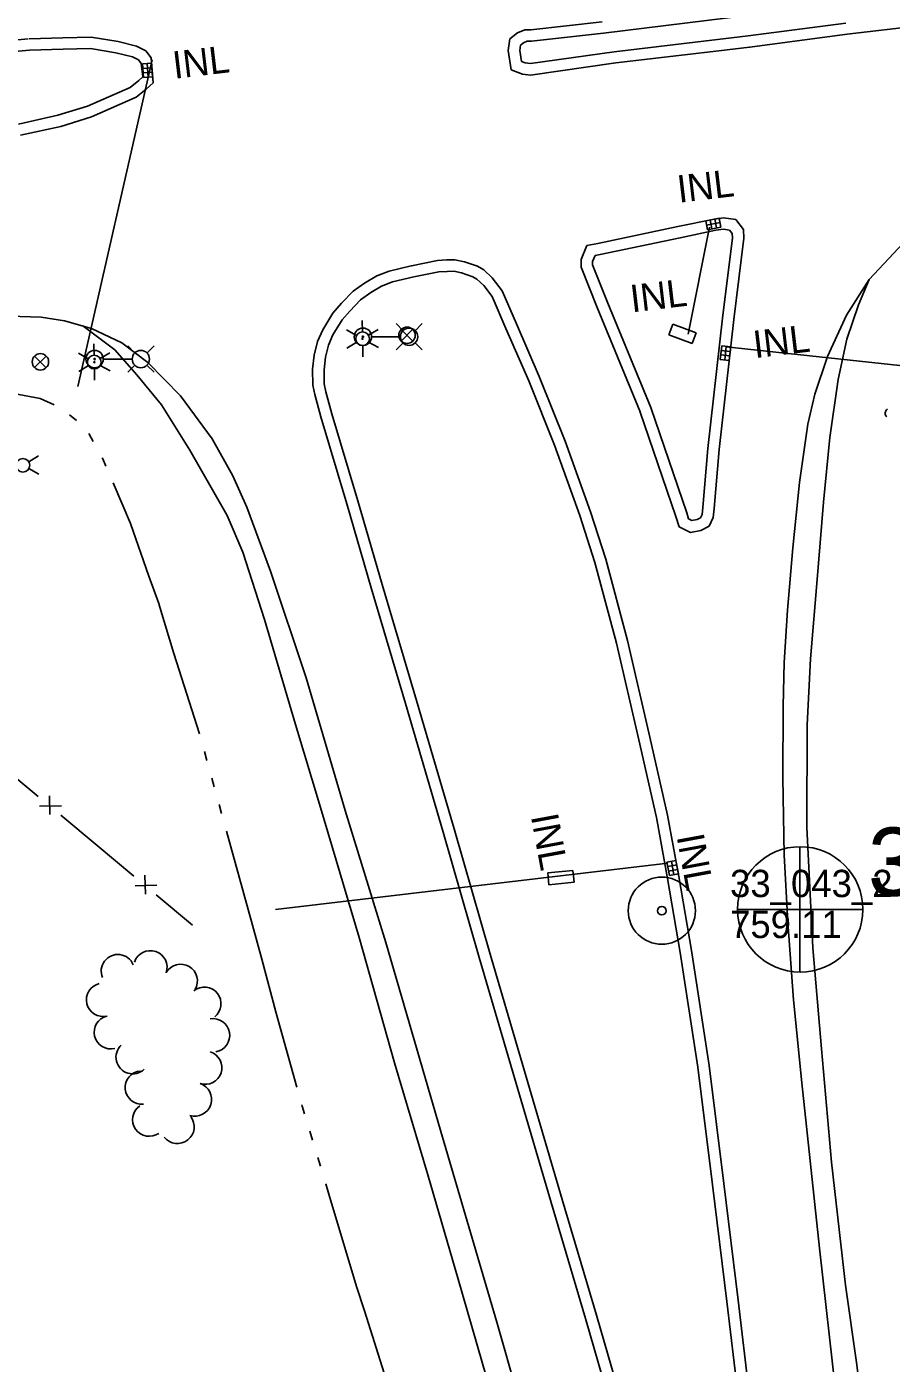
# Model space of a CAD drawing. Extents: x 589250 to 1188077, y 162953 to 363065.
# Drawn here: x 594538 to 594728, y 174624.2 to 174918 of the extents above; entities that cross this region are included whole.
import ezdxf

# ---------------------------------------------------------------- set-up
doc = ezdxf.new("R2010")
doc.units = 0
for name, color, linetype in [('E_DRN', 7, 'Continuous'), ('E_DRN_SS_UG', 7, 'Continuous'), ('E_DRN_Text', 7, 'Continuous'), ('E_FEN_P', 7, 'Continuous'), ('E_LAND_TreeLine_P', 7, 'Continuous'), ('E_LTG', 7, 'Continuous'), ('E_MAP_PassPoints', 7, 'Continuous'), ('E_MAP_PhotoCenter', 7, 'Continuous'), ('E_RDWY', 7, 'Continuous'), ('E_RDWY_C_and_G', 7, 'Continuous'), ('E_RDWY_Gravel', 7, 'Continuous'), ('E_SIG', 7, 'Continuous'), ('E_WTR_FlowLine', 7, 'Continuous')]:
    doc.layers.add(name, color=color, linetype=linetype)

# ---------------------------------------------------------------- blocks, each defined once
blk = doc.blocks.new('LPM_1')
at = {"layer": 'E_LTG'}
for p, q in [((32.9, 0), (7.7, 0)), ((35.3, 5.3), (29.1, 11.6)), ((46, 5.3), (52.2, 11.6)), ((35.3, -5.3), (29.1, -11.6)), ((46, -5.3), (52.2, -11.6))]:
    blk.add_line(p, q, dxfattribs=at)
for centre, radius in [((0, 0), 7.62), ((0, 0), 0.583), ((40.6, 0), 7.62)]:
    blk.add_circle(centre, radius, dxfattribs=at)
blk = doc.blocks.new('PBX_2')
at = {"layer": 'E_SIG'}
for p, q in [((4.9, 5.1), (-5.1, -5.1)), ((-5.1, 5), (5, -5.2))]:
    blk.add_line(p, q, dxfattribs=at)
blk.add_circle((0, 0), 7.21, dxfattribs=at)

msp = doc.modelspace()

# ---------------------------------------------------------------- linework, layer by layer
at = {"layer": 'E_DRN'}
for p, q in [((594565.41, 174909.94), (594563.41, 174909.8)), ((594563.41, 174909.8), (594563.62, 174906.81)), ((594563.48, 174908.8), (594565.48, 174908.95)), ((594563.55, 174907.81), (594565.55, 174907.95)), ((594564.62, 174906.88), (594564.41, 174909.87)), ((594565.62, 174906.95), (594565.41, 174909.94)), ((594563.62, 174906.81), (594565.62, 174906.95)), ((594690.15, 174875.88), (594687.2, 174875.29)), ((594687.2, 174875.29), (594687.59, 174873.33)), ((594688.57, 174873.53), (594688.18, 174875.49)), ((594689.56, 174873.72), (594689.17, 174875.68)), ((594690.54, 174873.92), (594690.15, 174875.88)), ((594690.34, 174874.9), (594687.4, 174874.31)), ((594687.59, 174873.33), (594690.54, 174873.92)), ((594679.1, 174850.24), (594679.99, 174852.58)), ((594679.99, 174852.58), (594685.11, 174850.64)), ((594684.22, 174848.3), (594679.1, 174850.24)), ((594685.11, 174850.64), (594684.22, 174848.3)), ((594690.73, 174847.81), (594690.39, 174844.82)), ((594690.5, 174845.82), (594692.49, 174845.59)), ((594690.61, 174846.81), (594692.6, 174846.59)), ((594692.71, 174847.58), (594690.73, 174847.81)), ((594691.38, 174844.71), (594691.72, 174847.69)), ((594692.37, 174844.6), (594692.71, 174847.58)), ((594690.39, 174844.82), (594692.37, 174844.6)), ((594680.64, 174734.72), (594678.67, 174734.36)), ((594678.67, 174734.36), (594679.22, 174731.41)), ((594680.2, 174731.59), (594679.66, 174734.54)), ((594681.19, 174731.77), (594680.64, 174734.72)), ((594658.01, 174732.52), (594652.47, 174731.97)), ((594652.47, 174731.97), (594652.73, 174729.38)), ((594658.26, 174729.93), (594658.01, 174732.52)), ((594678.86, 174733.37), (594680.82, 174733.74)), ((594679.04, 174732.39), (594681, 174732.75)), ((594679.22, 174731.41), (594681.19, 174731.77)), ((594652.73, 174729.38), (594658.26, 174729.93))]:
    msp.add_line(p, q, dxfattribs=at)
msp.add_arc((594727.7, 174833), 1.04, 122.955, 229.2152, dxfattribs=at)
at = {"layer": 'E_DRN_SS_UG'}
for p, q in [((594565.55, 174910.71), (594549.19, 174838.9)), ((594683.36, 174850.39), (594688.06, 174873.91)), ((594691.68, 174847.61), (594766.96, 174839.54)), ((594678.84, 174734.13), (594592.64, 174723.97))]:
    msp.add_line(p, q, dxfattribs=at)
at = {"layer": 'E_FEN_P'}
for p, q in [((594532.46, 174755.44), (594540.47, 174748.77)), ((594542.92, 174748.95), (594543.04, 174744.82)), ((594540.77, 174746.62), (594545.59, 174746.73)), ((594545.44, 174744.64), (594553.45, 174737.97)), ((594553.45, 174737.97), (594561.47, 174731.29)), ((594563.92, 174731.47), (594564.04, 174727.34)), ((594561.77, 174729.14), (594566.58, 174729.25)), ((594566.43, 174727.16), (594574.42, 174720.46))]:
    msp.add_line(p, q, dxfattribs=at)
at = {"layer": 'E_LAND_TreeLine_P'}
for centre, start, end in [((594557.99, 174710.39), 22.8086, 202.8086), ((594565.13, 174711.22), 341.3534, 161.3534), ((594571.79, 174708.23), 329.5776, 149.5776), ((594554.74, 174704.09), 103.536, 283.536), ((594576.99, 174703.22), 308.4125, 128.4125), ((594556.45, 174696.95), 103.536, 283.536), ((594578.91, 174696.29), 279.5379, 99.5379), ((594561.24, 174691.49), 133.4046, 313.4046), ((594577.17, 174689.18), 252.1211, 72.1211), ((594563.27, 174684.79), 95.4059, 275.4059), ((594574.92, 174682.19), 252.1211, 72.1211), ((594564.9, 174677.76), 124.6972, 304.6972), ((594571.09, 174676.18), 217.8771, 37.8771)]:
    msp.add_arc(centre, 3.67, start, end, dxfattribs=at)
at = {"layer": 'E_LTG'}
for p, q in [((594611.74, 174850.87), (594611.7, 174853.37)), ((594610.46, 174850.09), (594608.27, 174851.31)), ((594615.2, 174851.43), (594613.06, 174850.14)), ((594551.49, 174844.97), (594549.3, 174846.18)), ((594552.77, 174845.74), (594552.73, 174848.24)), ((594556.23, 174846.3), (594554.08, 174845.02)), ((594610.49, 174848.59), (594608.34, 174847.31)), ((594611.84, 174845.37), (594611.8, 174847.87)), ((594615.27, 174847.43), (594613.08, 174848.64)), ((594551.51, 174843.47), (594549.37, 174842.18)), ((594556.3, 174842.31), (594554.11, 174843.52)), ((594552.87, 174840.24), (594552.83, 174842.74)), ((594540.54, 174823.62), (594538.4, 174822.33)), ((594540.61, 174819.62), (594538.43, 174820.83))]:
    msp.add_line(p, q, dxfattribs=at)
for centre, radius in [((594611.77, 174849.37), 1.5), ((594611.77, 174849.37), 0.125), ((594552.8, 174844.24), 1.5), ((594552.8, 174844.24), 0.125), ((594537.11, 174821.56), 1.5)]:
    msp.add_circle(centre, radius, dxfattribs=at)
at = {"layer": 'E_MAP_PassPoints'}
for radius in [7.38, 7.38, 0.945, 0.945]:
    msp.add_circle((594677.55, 174723.68), radius, dxfattribs=at)
at = {"layer": 'E_MAP_PhotoCenter'}
for p, q in [((594707.92, 174737.76), (594707.86, 174710.35)), ((594694.23, 174723.95), (594721.69, 174723.94))]:
    msp.add_line(p, q, dxfattribs=at)
msp.add_circle((594707.97, 174723.96), 13.78, dxfattribs=at)
at = {"layer": 'E_RDWY'}
for p, q in [((594723.09, 174862.4), (594730.6, 174870.37)), ((594718.14, 174854.58), (594723.09, 174862.4)), ((594531.74, 174854.42), (594541.14, 174854.09)), ((594541.14, 174854.09), (594546.26, 174853.35)), ((594546.26, 174853.35), (594552.22, 174851.64)), ((594713.93, 174845.5), (594718.14, 174854.58)), ((594552.22, 174851.64), (594558.87, 174848.47)), ((594558.87, 174848.47), (594564.55, 174844.12)), ((594564.55, 174844.12), (594571.76, 174836.83)), ((594711.17, 174837.22), (594713.93, 174845.5)), ((594709.62, 174830.59), (594711.17, 174837.22)), ((594571.76, 174836.83), (594578.68, 174827.39)), ((594707.84, 174817.81), (594709.62, 174830.59)), ((594578.68, 174827.39), (594583.28, 174819.23)), ((594583.28, 174819.23), (594586.36, 174812.36)), ((594706.33, 174803.39), (594707.84, 174817.81)), ((594586.36, 174812.36), (594591.56, 174798.28)), ((594705.19, 174789.7), (594706.33, 174803.39)), ((594591.56, 174798.28), (594599.38, 174774.86)), ((594704.46, 174778.22), (594705.19, 174789.7)), ((594704.25, 174768.64), (594704.46, 174778.22)), ((594599.38, 174774.86), (594607.97, 174745.67)), ((594704.15, 174752.86), (594704.25, 174768.64)), ((594704.45, 174735.95), (594704.15, 174752.86)), ((594607.97, 174745.67), (594616.89, 174716.66)), ((594705.27, 174721.13), (594704.45, 174735.95)), ((594706.51, 174704.05), (594705.27, 174721.13)), ((594616.89, 174716.66), (594628.99, 174675.18)), ((594708.33, 174685.86), (594706.51, 174704.05)), ((594712.17, 174649.48), (594708.33, 174685.86)), ((594628.99, 174675.18), (594641.26, 174633.21)), ((594716.16, 174614.61), (594712.17, 174649.48)), ((594641.26, 174633.21), (594655.48, 174583.86))]:
    msp.add_line(p, q, dxfattribs=at)
at = {"layer": 'E_RDWY_C_and_G'}
for p, q in [((594696.29, 174920.4), (594664.72, 174916.55)), ((594752.76, 174920.45), (594718.31, 174916.29)), ((594645.85, 174916.6), (594644.12, 174915.26)), ((594647.42, 174917.26), (594645.85, 174916.6)), ((594648.77, 174917.29), (594647.42, 174917.26)), ((594664.43, 174919.03), (594648.77, 174917.29)), ((594664.72, 174916.55), (594648.93, 174914.79)), ((594717.99, 174918.77), (594696.54, 174915.95)), ((594526.33, 174914.19), (594538.3, 174915.3)), ((594538.45, 174915.31), (594545.88, 174915.54)), ((594545.88, 174915.54), (594552.15, 174915.65)), ((594552.15, 174915.65), (594558.03, 174914.7)), ((594558.03, 174914.7), (594562.09, 174913.68)), ((594562.09, 174913.68), (594564.13, 174912.63)), ((594644.12, 174915.26), (594643.81, 174912.73)), ((594646.48, 174913.92), (594646.33, 174912.76)), ((594647.13, 174914.43), (594646.48, 174913.92)), ((594647.94, 174914.77), (594647.13, 174914.43)), ((594648.93, 174914.79), (594647.94, 174914.77)), ((594667.1, 174912.47), (594689.79, 174915.18)), ((594689.79, 174915.18), (594696.54, 174915.95)), ((594690.09, 174912.69), (594696.82, 174913.47)), ((594718.31, 174916.29), (594696.86, 174913.48)), ((594526.59, 174911.71), (594538.53, 174912.81)), ((594538.53, 174912.81), (594545.94, 174913.04)), ((594545.94, 174913.04), (594551.97, 174913.14)), ((594551.97, 174913.14), (594557.52, 174912.25)), ((594557.52, 174912.25), (594561.2, 174911.33)), ((594561.2, 174911.33), (594562.5, 174910.66)), ((594562.5, 174910.66), (594563.1, 174909.88)), ((594564.13, 174912.63), (594565.33, 174911.09)), ((594565.33, 174911.09), (594565.71, 174905.6)), ((594643.81, 174912.73), (594644.45, 174908.48)), ((594646.33, 174912.76), (594646.7, 174910.3)), ((594648.69, 174909.84), (594667.1, 174912.47)), ((594667.43, 174909.99), (594690.09, 174912.69)), ((594563.1, 174909.88), (594563.45, 174906.92)), ((594644.45, 174908.48), (594646.93, 174907.54)), ((594646.7, 174910.3), (594647.53, 174909.98)), ((594646.93, 174907.54), (594648.71, 174907.32)), ((594647.53, 174909.98), (594648.69, 174909.84)), ((594648.71, 174907.32), (594667.43, 174909.99)), ((594560.72, 174904.6), (594551.3, 174900.47)), ((594562.58, 174906.11), (594560.72, 174904.6)), ((594563.45, 174906.92), (594562.58, 174906.11)), ((594565.71, 174905.6), (594564.22, 174904.22)), ((594562.04, 174902.44), (594552.18, 174898.13)), ((594564.22, 174904.22), (594562.04, 174902.44)), ((594551.3, 174900.47), (594544.81, 174898.48)), ((594544.81, 174898.48), (594536.15, 174896.55)), ((594545.45, 174896.06), (594536.6, 174894.09)), ((594552.18, 174898.13), (594545.45, 174896.06)), ((594681.08, 174874.01), (594689.03, 174875.67)), ((594689.03, 174875.67), (594691.13, 174875.95)), ((594691.13, 174875.95), (594693.79, 174875.61)), ((594693.79, 174875.61), (594695.51, 174873.4)), ((594663.51, 174870.33), (594681.07, 174874.01)), ((594681.59, 174871.57), (594689.45, 174873.21)), ((594689.45, 174873.21), (594691.13, 174873.43)), ((594691.13, 174873.43), (594692.45, 174873.26)), ((594692.45, 174873.26), (594693.03, 174872.52)), ((594693.03, 174872.52), (594693.05, 174871.58)), ((594695.51, 174873.4), (594695.55, 174871.45)), ((594659.82, 174866.81), (594661.07, 174869.88)), ((594661.07, 174869.88), (594663.51, 174870.33)), ((594663.99, 174867.88), (594681.59, 174871.57)), ((594693.05, 174871.58), (594690.91, 174853.88)), ((594695.55, 174871.45), (594693.4, 174853.59)), ((594622.53, 174865.43), (594628.23, 174866.55)), ((594628.23, 174866.55), (594630.26, 174866.69)), ((594630.26, 174866.69), (594632.03, 174866.72)), ((594632.03, 174866.72), (594634.19, 174866.3)), ((594659.85, 174865.09), (594659.82, 174866.81)), ((594662.33, 174866.34), (594662.87, 174867.67)), ((594662.87, 174867.67), (594663.99, 174867.88)), ((594614.87, 174863.21), (594617.63, 174864.25)), ((594617.63, 174864.25), (594622.43, 174865.41)), ((594623.02, 174862.98), (594628.55, 174864.07)), ((594628.55, 174864.07), (594630.36, 174864.19)), ((594630.36, 174864.19), (594631.81, 174864.21)), ((594631.81, 174864.21), (594633.54, 174863.88)), ((594633.54, 174863.88), (594636, 174863.02)), ((594634.19, 174866.3), (594637.05, 174865.3)), ((594637.05, 174865.3), (594638.43, 174864.5)), ((594638.43, 174864.5), (594640.26, 174862.74)), ((594663.36, 174856.26), (594659.85, 174865.09)), ((594662.34, 174865.59), (594662.33, 174866.34)), ((594665.68, 174857.2), (594662.34, 174865.59)), ((594609.7, 174859.83), (594612.19, 174861.62)), ((594612.19, 174861.62), (594614.87, 174863.21)), ((594613.56, 174859.52), (594615.96, 174860.95)), ((594615.96, 174860.95), (594618.36, 174861.86)), ((594618.36, 174861.86), (594623.02, 174862.98)), ((594636, 174863.02), (594636.92, 174862.49)), ((594636.92, 174862.49), (594638.39, 174861.07)), ((594638.39, 174861.07), (594640.25, 174858.65)), ((594640.26, 174862.74), (594642.42, 174859.93)), ((594607.12, 174857.16), (594609.7, 174859.83)), ((594608.96, 174855.46), (594611.34, 174857.93)), ((594611.34, 174857.93), (594613.56, 174859.52)), ((594640.25, 174858.65), (594643.27, 174851.64)), ((594642.42, 174859.93), (594645.57, 174852.63)), ((594603.02, 174851.36), (594605.24, 174855.01)), ((594605.24, 174855.01), (594607.12, 174857.16)), ((594607.26, 174853.53), (594608.96, 174855.46)), ((594672.79, 174833.31), (594663.36, 174856.26)), ((594675.1, 174834.26), (594665.68, 174857.2)), ((594605.25, 174850.21), (594607.26, 174853.53)), ((594645.57, 174852.63), (594650.59, 174841.09)), ((594690.91, 174853.88), (594687.66, 174825.27)), ((594693.4, 174853.59), (594690.15, 174825.03)), ((594601.87, 174848.75), (594603.02, 174851.36)), ((594604.25, 174847.94), (594605.25, 174850.21)), ((594643.27, 174851.64), (594648.28, 174840.12)), ((594601.13, 174845.77), (594601.87, 174848.75)), ((594603.6, 174845.33), (594604.25, 174847.94)), ((594600.8, 174842.67), (594601.13, 174845.77)), ((594603.3, 174842.56), (594603.6, 174845.33)), ((594600.86, 174839.15), (594600.8, 174842.67)), ((594603.36, 174839.45), (594603.3, 174842.56)), ((594648.28, 174840.12), (594653.97, 174825.99)), ((594650.59, 174841.09), (594656.3, 174826.88)), ((594601.31, 174837.13), (594600.86, 174839.15)), ((594602.63, 174832.22), (594601.31, 174837.13)), ((594603.73, 174837.72), (594603.36, 174839.45)), ((594605.03, 174832.9), (594603.73, 174837.72)), ((594683.02, 174811.1), (594675.1, 174834.26)), ((594608.34, 174813.08), (594602.63, 174832.22)), ((594610.73, 174813.79), (594605.03, 174832.9)), ((594680.65, 174810.33), (594672.74, 174833.45)), ((594653.97, 174825.99), (594659.49, 174810.5)), ((594656.3, 174826.88), (594661.86, 174811.31)), ((594687.66, 174825.27), (594686.57, 174812.29)), ((594690.15, 174825.03), (594689.06, 174812.05)), ((594616.07, 174795.37), (594610.73, 174813.79)), ((594613.67, 174794.67), (594608.33, 174813.1)), ((594661.86, 174811.31), (594665.25, 174800.94)), ((594683.42, 174809.79), (594683.02, 174811.1)), ((594686.41, 174810.78), (594686.05, 174810.03)), ((594686.57, 174812.29), (594686.41, 174810.78)), ((594689.06, 174812.05), (594688.85, 174810.09)), ((594659.49, 174810.5), (594662.85, 174800.23)), ((594681.35, 174808.01), (594680.65, 174810.33)), ((594683.84, 174806.82), (594681.35, 174808.01)), ((594684.18, 174809.43), (594683.42, 174809.79)), ((594685.3, 174809.64), (594684.18, 174809.43)), ((594686.05, 174810.03), (594685.3, 174809.64)), ((594687.95, 174808.19), (594686.13, 174807.25)), ((594688.85, 174810.09), (594687.95, 174808.19)), ((594686.13, 174807.25), (594683.84, 174806.82)), ((594662.85, 174800.23), (594667.6, 174782.45)), ((594665.25, 174800.94), (594670.03, 174783.06)), ((594621.22, 174769.19), (594613.67, 174794.67)), ((594623.61, 174769.9), (594616.07, 174795.37)), ((594667.6, 174782.45), (594672.51, 174761.24)), ((594670.03, 174783.06), (594674.94, 174761.8)), ((594631.9, 174741.66), (594623.61, 174769.9)), ((594629.5, 174740.97), (594621.22, 174769.19)), ((594672.51, 174761.24), (594676.35, 174744.19)), ((594674.94, 174761.8), (594678.8, 174744.69)), ((594676.35, 174744.19), (594678.83, 174730.74)), ((594678.8, 174744.69), (594681.29, 174731.17)), ((594637.42, 174713.42), (594629.5, 174740.97)), ((594639.82, 174714.12), (594631.9, 174741.66)), ((594678.83, 174730.74), (594681.58, 174714.5)), ((594681.29, 174731.17), (594684.05, 174714.9)), ((594646.45, 174691.39), (594639.82, 174714.12)), ((594681.58, 174714.5), (594685.45, 174689.29)), ((594684.05, 174714.9), (594687.93, 174689.64)), ((594644.05, 174690.69), (594637.42, 174713.42)), ((594653.25, 174659.53), (594644.05, 174690.69)), ((594655.65, 174660.24), (594646.45, 174691.39)), ((594685.45, 174689.29), (594688.69, 174663.43)), ((594687.93, 174689.64), (594691.17, 174663.73)), ((594691.17, 174663.73), (594694.3, 174638.07)), ((594688.69, 174663.43), (594691.82, 174637.77)), ((594660.79, 174634.06), (594653.25, 174659.53)), ((594663.19, 174634.76), (594655.65, 174660.24)), ((594691.82, 174637.77), (594695.46, 174607.52)), ((594694.3, 174638.07), (594697.94, 174607.83)), ((594670.19, 174610.49), (594663.19, 174634.76)), ((594667.79, 174609.79), (594660.79, 174634.06))]:
    msp.add_line(p, q, dxfattribs=at)
at = {"layer": 'E_RDWY_Gravel'}
for p, q in [((594720.75, 174856.81), (594723.09, 174862.4)), ((594718.21, 174849.29), (594720.75, 174856.81)), ((594550.28, 174852.2), (594557.35, 174846.93)), ((594716.3, 174840.42), (594718.21, 174849.29)), ((594557.35, 174846.93), (594562.12, 174841.48)), ((594562.12, 174841.48), (594567.6, 174834.83)), ((594714.46, 174827.64), (594716.3, 174840.42)), ((594567.6, 174834.83), (594573.83, 174824.9)), ((594713.11, 174813.46), (594714.46, 174827.64)), ((594573.83, 174824.9), (594582.04, 174810.51)), ((594711.6, 174795.56), (594713.11, 174813.46)), ((594582.04, 174810.51), (594585.47, 174802.44)), ((594585.47, 174802.44), (594590.23, 174787.64)), ((594710.23, 174779.06), (594711.6, 174795.56)), ((594590.23, 174787.64), (594597.04, 174764.57)), ((594709.46, 174764.52), (594710.23, 174779.06)), ((594597.04, 174764.57), (594602.55, 174746.33)), ((594709.44, 174742.07), (594709.46, 174764.52)), ((594602.55, 174746.33), (594611.01, 174717.75)), ((594710.76, 174715.52), (594709.44, 174742.07)), ((594611.01, 174717.75), (594618.76, 174690.21)), ((594712.65, 174693.33), (594710.76, 174715.52)), ((594714.84, 174668.4), (594712.65, 174693.33)), ((594618.76, 174690.21), (594626.12, 174665.59)), ((594717.95, 174641.41), (594714.84, 174668.4)), ((594626.12, 174665.59), (594632.75, 174642.69)), ((594632.75, 174642.69), (594641.41, 174612.74)), ((594720.34, 174624.35), (594717.95, 174641.41)), ((594723.34, 174601.65), (594720.34, 174624.35))]:
    msp.add_line(p, q, dxfattribs=at)
at = {"layer": 'E_WTR_FlowLine'}
for p, q in [((594535.02, 174837.37), (594540.93, 174836.26)), ((594540.93, 174836.26), (594543.97, 174834.86)), ((594547.32, 174832.68), (594548.86, 174831.38)), ((594551.62, 174828.53), (594552.59, 174826.76)), ((594554.53, 174823.23), (594554.66, 174823.01)), ((594554.66, 174823.01), (594555.35, 174821.39)), ((594556.94, 174817.69), (594560.79, 174808.75)), ((594560.79, 174808.75), (594564.8, 174797.23)), ((594564.8, 174797.23), (594566.98, 174791.21)), ((594566.98, 174791.21), (594567.22, 174790.41)), ((594567.22, 174790.41), (594570.29, 174780.2)), ((594570.29, 174780.2), (594575.9, 174762.52)), ((594576.99, 174758.65), (594577.53, 174756.71)), ((594578.62, 174752.83), (594579.16, 174750.89)), ((594580.24, 174747.01), (594580.79, 174745.07)), ((594581.87, 174741.19), (594587.6, 174720.46)), ((594587.6, 174720.46), (594589.6, 174713.03)), ((594589.6, 174713.03), (594592.79, 174701.17)), ((594592.79, 174701.17), (594597.34, 174684.87)), ((594598.43, 174680.99), (594598.51, 174680.68)), ((594598.51, 174680.68), (594599.01, 174679.06)), ((594600.18, 174675.21), (594600.77, 174673.28)), ((594601.94, 174669.43), (594602.53, 174667.5)), ((594603.7, 174663.65), (594604.39, 174661.4)), ((594604.39, 174661.4), (594610.46, 174641.09)), ((594610.46, 174641.09), (594612.17, 174635.7)), ((594612.17, 174635.7), (594617.42, 174619.24))]:
    msp.add_line(p, q, dxfattribs=at)

# ---------------------------------------------------------------- block references
at = {"layer": 'E_LTG', "xscale": 0.25, "yscale": 0.25}
for p in [(594611.85, 174849.82), (594552.88, 174844.9)]:
    msp.add_blockref('LPM_1', p, dxfattribs=at)
at = {"layer": 'E_SIG', "xscale": 0.25, "yscale": 0.25}
for p in [(594621.54, 174850.14), (594540.97, 174844.3)]:
    msp.add_blockref('PBX_2', p, dxfattribs=at)

# ---------------------------------------------------------------- texts
at = {"layer": 'E_DRN_Text'}
for rotation, p in [(6.7836, (594570.39, 174906.49)), (6.7836, (594681.29, 174879.25)), (6.7836, (594670.96, 174855.17)), (6.7836, (594697.98, 174845.1)), (280.4887, (594648.74, 174744.45)), (280.4887, (594680.78, 174740.02))]:
    msp.add_text('INL', height=6, rotation=rotation, dxfattribs=at).set_placement(p)
at = {"layer": 'E_MAP_PassPoints'}
for s, p in [('33_043_2', (594692.55, 174726.66)), ('33_043_2', (594692.55, 174726.66)), ('759.11', (594692.55, 174717.66)), ('759.11', (594692.55, 174717.66))]:
    msp.add_text(s, height=6, dxfattribs=at).set_placement(p)
at = {"layer": 'E_MAP_PhotoCenter'}
msp.add_text('33_043', height=15, dxfattribs=at).set_placement((594722.83, 174726.94))

doc.saveas('drawing.dxf')
